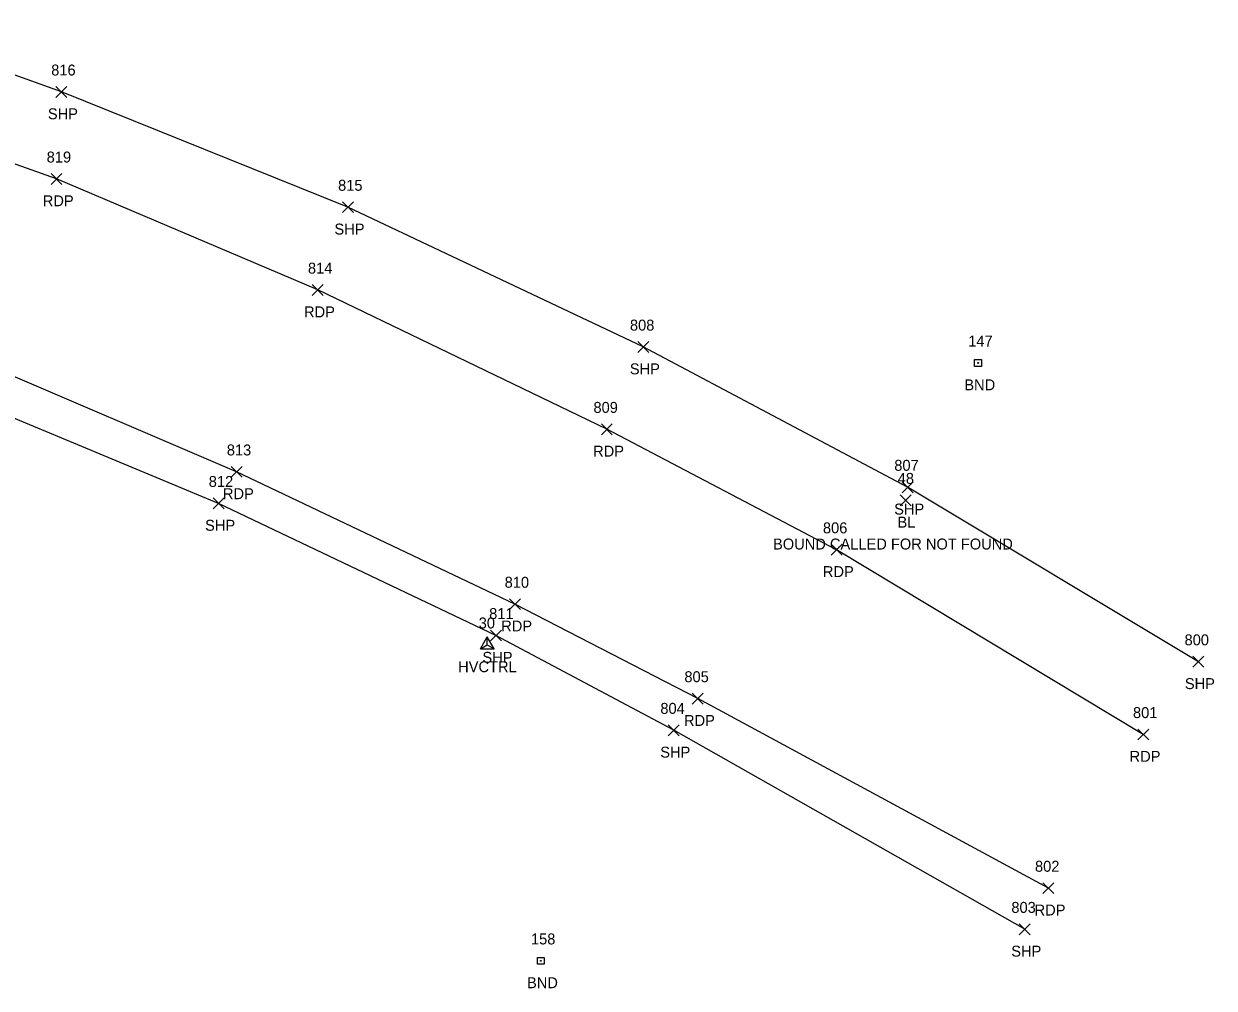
# Model space of a CAD drawing. Extents: x 49137 to 50946, y 9590 to 10709.
# Drawn here: x 50728.4 to 50945.9, y 9869.3 to 10045.7 of the extents above; entities that cross this region are included whole.
import ezdxf

# ---------------------------------------------------------------- set-up
doc = ezdxf.new("R2010")
doc.units = 0
for name, color, linetype in [('C_A', 7, 'Continuous'), ('C_C', 7, 'Continuous'), ('C_I', 7, 'Continuous'), ('C_TIC', 7, 'Continuous'), ('CPSM', 7, 'Continuous'), ('M_A', 7, 'Continuous'), ('M_I', 7, 'Continuous'), ('MHBP', 7, 'Continuous'), ('P_A', 7, 'Continuous'), ('P_I', 7, 'Continuous'), ('P_TIC', 7, 'Continuous'), ('PET', 7, 'Continuous'), ('PSP', 7, 'Continuous')]:
    doc.layers.add(name, color=color, linetype=linetype)

msp = doc.modelspace()

# ---------------------------------------------------------------- linework, layer by layer
at = {"layer": 'C_TIC'}
for points in [[(50888.56, 9957.54), (50890.56, 9959.54)], [(50890.56, 9957.54), (50888.56, 9959.54)]]:
    msp.add_lwpolyline(points, dxfattribs=at)
at = {"layer": 'CPSM'}
for p, q in [((50811.81, 9931.39), (50813.06, 9933.55)), ((50811.81, 9931.39), (50813.06, 9932.11)), ((50814.31, 9931.39), (50813.06, 9933.55)), ((50813.06, 9932.11), (50813.06, 9933.55)), ((50813.06, 9932.11), (50813.06, 9932.11)), ((50813.06, 9932.11), (50814.31, 9931.39)), ((50811.81, 9931.39), (50814.31, 9931.39))]:
    msp.add_line(p, q, dxfattribs=at)
at = {"layer": 'MHBP'}
for points in [[(50902.15, 9984.28), (50903.4, 9984.28), (50903.4, 9983.03), (50902.15, 9983.03)], [(50822.23, 9874.95), (50823.48, 9874.95), (50823.48, 9873.7), (50822.23, 9873.7)]]:
    msp.add_lwpolyline(points, close=True, dxfattribs=at)
for centre in [(50902.77, 9983.65), (50822.86, 9874.33)]:
    msp.add_circle(centre, 0.0833, dxfattribs=at)
at = {"layer": 'P_TIC'}
for points in [[(50734.23, 10032.21), (50736.23, 10034.21)], [(50736.23, 10032.21), (50734.23, 10034.21)], [(50733.35, 10016.3), (50735.35, 10018.3)], [(50735.35, 10016.3), (50733.35, 10018.3)], [(50786.61, 10011.13), (50788.61, 10013.13)], [(50788.61, 10011.13), (50786.61, 10013.13)], [(50781.09, 9995.99), (50783.09, 9997.99)], [(50783.09, 9995.99), (50781.09, 9997.99)], [(50840.59, 9985.57), (50842.59, 9987.57)], [(50842.59, 9985.57), (50840.59, 9987.57)], [(50833.93, 9970.52), (50835.93, 9972.52)], [(50835.93, 9970.52), (50833.93, 9972.52)], [(50766.27, 9962.74), (50768.27, 9964.74)], [(50768.27, 9962.74), (50766.27, 9964.74)], [(50888.9, 9959.93), (50890.9, 9961.93)], [(50890.9, 9959.93), (50888.9, 9961.93)], [(50762.96, 9956.97), (50764.96, 9958.97)], [(50764.96, 9956.97), (50762.96, 9958.97)], [(50875.92, 9948.5), (50877.92, 9950.5)], [(50877.92, 9948.5), (50875.92, 9950.5)], [(50817.14, 9938.55), (50819.14, 9940.55)], [(50819.14, 9938.55), (50817.14, 9940.55)], [(50813.65, 9932.82), (50815.65, 9934.82)], [(50815.65, 9932.82), (50813.65, 9934.82)], [(50942.04, 9928.02), (50944.04, 9930.02)], [(50944.04, 9928.02), (50942.04, 9930.02)], [(50850.54, 9921.28), (50852.54, 9923.28)], [(50852.54, 9921.28), (50850.54, 9923.28)], [(50846.15, 9915.49), (50848.15, 9917.49)], [(50848.15, 9915.49), (50846.15, 9917.49)], [(50931.97, 9914.72), (50933.97, 9916.72)], [(50933.97, 9914.72), (50931.97, 9916.72)], [(50914.62, 9886.62), (50916.62, 9888.62)], [(50916.62, 9886.62), (50914.62, 9888.62)], [(50910.3, 9879.1), (50912.3, 9881.1)], [(50912.3, 9879.1), (50910.3, 9881.1)]]:
    msp.add_lwpolyline(points, dxfattribs=at)
at = {"layer": 'PET'}
for points in [[(50932.97, 9915.72), (50876.92, 9949.5), (50834.93, 9971.52), (50782.09, 9996.99), (50734.35, 10017.3), (50680.97, 10036.27)], [(50915.62, 9887.62), (50851.54, 9922.28), (50818.14, 9939.55), (50767.27, 9963.74), (50720.82, 9983.62), (50672.38, 10001.53)]]:
    msp.add_lwpolyline(points, dxfattribs=at)
at = {"layer": 'PSP'}
for points in [[(50943.04, 9929.02), (50889.9, 9960.93), (50841.59, 9986.57), (50787.61, 10012.13), (50735.23, 10033.21), (50721.79, 10038.01), (50696.69, 10045.66)], [(50911.3, 9880.1), (50847.15, 9916.49), (50814.65, 9933.82), (50763.96, 9957.97), (50718.01, 9977.08), (50670.09, 9994.37)]]:
    msp.add_lwpolyline(points, dxfattribs=at)

# ---------------------------------------------------------------- texts
at = {"layer": 'C_A'}
for s, p in [('BL', (50888.05, 9953.54)), ('HVCTRL', (50807.75, 9927.11))]:
    msp.add_text(s, height=2, dxfattribs=at).set_placement(p)
at = {"layer": 'C_C'}
msp.add_text('BOUND CALLED FOR NOT FOUND', height=2, dxfattribs=at).set_placement((50865.3, 9949.54))
at = {"layer": 'C_I'}
for s, p in [('48', (50888.09, 9961.54)), ('30', (50811.51, 9935.11))]:
    msp.add_text(s, height=2, dxfattribs=at).set_placement(p)
at = {"layer": 'M_A'}
for p in [(50900.26, 9978.65), (50820.34, 9869.33)]:
    msp.add_text('BND', height=2, dxfattribs=at).set_placement(p)
at = {"layer": 'M_I'}
for s, p in [('147', (50900.98, 9986.65)), ('158', (50821.06, 9877.33))]:
    msp.add_text(s, height=2, dxfattribs=at).set_placement(p)
at = {"layer": 'P_A'}
for s, p in [('SHP', (50732.77, 10028.21)), ('RDP', (50731.84, 10012.3)), ('SHP', (50785.14, 10007.13)), ('RDP', (50779.58, 9991.99)), ('SHP', (50839.13, 9981.57)), ('RDP', (50832.42, 9966.52)), ('RDP', (50764.76, 9958.74)), ('SHP', (50887.44, 9955.93)), ('SHP', (50761.5, 9952.97)), ('RDP', (50874.41, 9944.5)), ('RDP', (50815.62, 9934.55)), ('SHP', (50812.19, 9928.82)), ('SHP', (50940.57, 9924.02)), ('RDP', (50849.03, 9917.28)), ('SHP', (50844.69, 9911.49)), ('RDP', (50930.46, 9910.72)), ('RDP', (50913.1, 9882.62)), ('SHP', (50908.84, 9875.1))]:
    msp.add_text(s, height=2, dxfattribs=at).set_placement(p)
at = {"layer": 'P_I'}
for s, p in [('816', (50733.38, 10036.21)), ('819', (50732.55, 10020.3)), ('815', (50785.81, 10015.13)), ('814', (50780.3, 9999.99)), ('808', (50839.15, 9989.57)), ('809', (50832.48, 9974.52)), ('813', (50765.47, 9966.74)), ('807', (50887.46, 9963.93)), ('812', (50762.17, 9960.97)), ('806', (50874.42, 9952.5)), ('810', (50816.25, 9942.55)), ('811', (50813.42, 9936.82)), ('800', (50940.51, 9932.02)), ('805', (50849.1, 9925.28)), ('804', (50844.71, 9919.49)), ('801', (50931.09, 9918.72)), ('802', (50913.18, 9890.62)), ('803', (50908.86, 9883.1))]:
    msp.add_text(s, height=2, dxfattribs=at).set_placement(p)

doc.saveas('drawing.dxf')
